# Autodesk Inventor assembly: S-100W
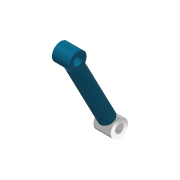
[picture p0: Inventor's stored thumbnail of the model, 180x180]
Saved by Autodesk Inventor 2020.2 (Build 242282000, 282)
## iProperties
Created: 2014-01
Part Number: S-100W
Document SubType Name: Assembly
Designer: F.Stasiak
Manager: www.cadconsulting.pl
Company: Fabian Stasiak CAD Consulting
Author: F.Stasiak
Subject: Zbiór ćwiczeń. Autodesk Inventor 2020. Kurs podstawowy
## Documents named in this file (3)
- C:\2020_Kurs_podstawowy\R6 Zespoły\Warsztat\Komponenty\S-100W.iam
- C:\2020_Kurs_podstawowy\R6 Zespoły\Warsztat\Komponenty\S-100.ipt
- C:\2020_Kurs_podstawowy\R6 Zespoły\Warsztat\Komponenty\S-101.ipt
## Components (2 placed, 2 different names)
1. S-100:1 — NAPĘD
2. S-101:1 — NAPĘD
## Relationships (1: Mate 1)
- NAPĘD [Mate]: S-100:1 ↔ S-101:1
